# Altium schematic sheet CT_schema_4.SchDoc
size 278 x 192 mm
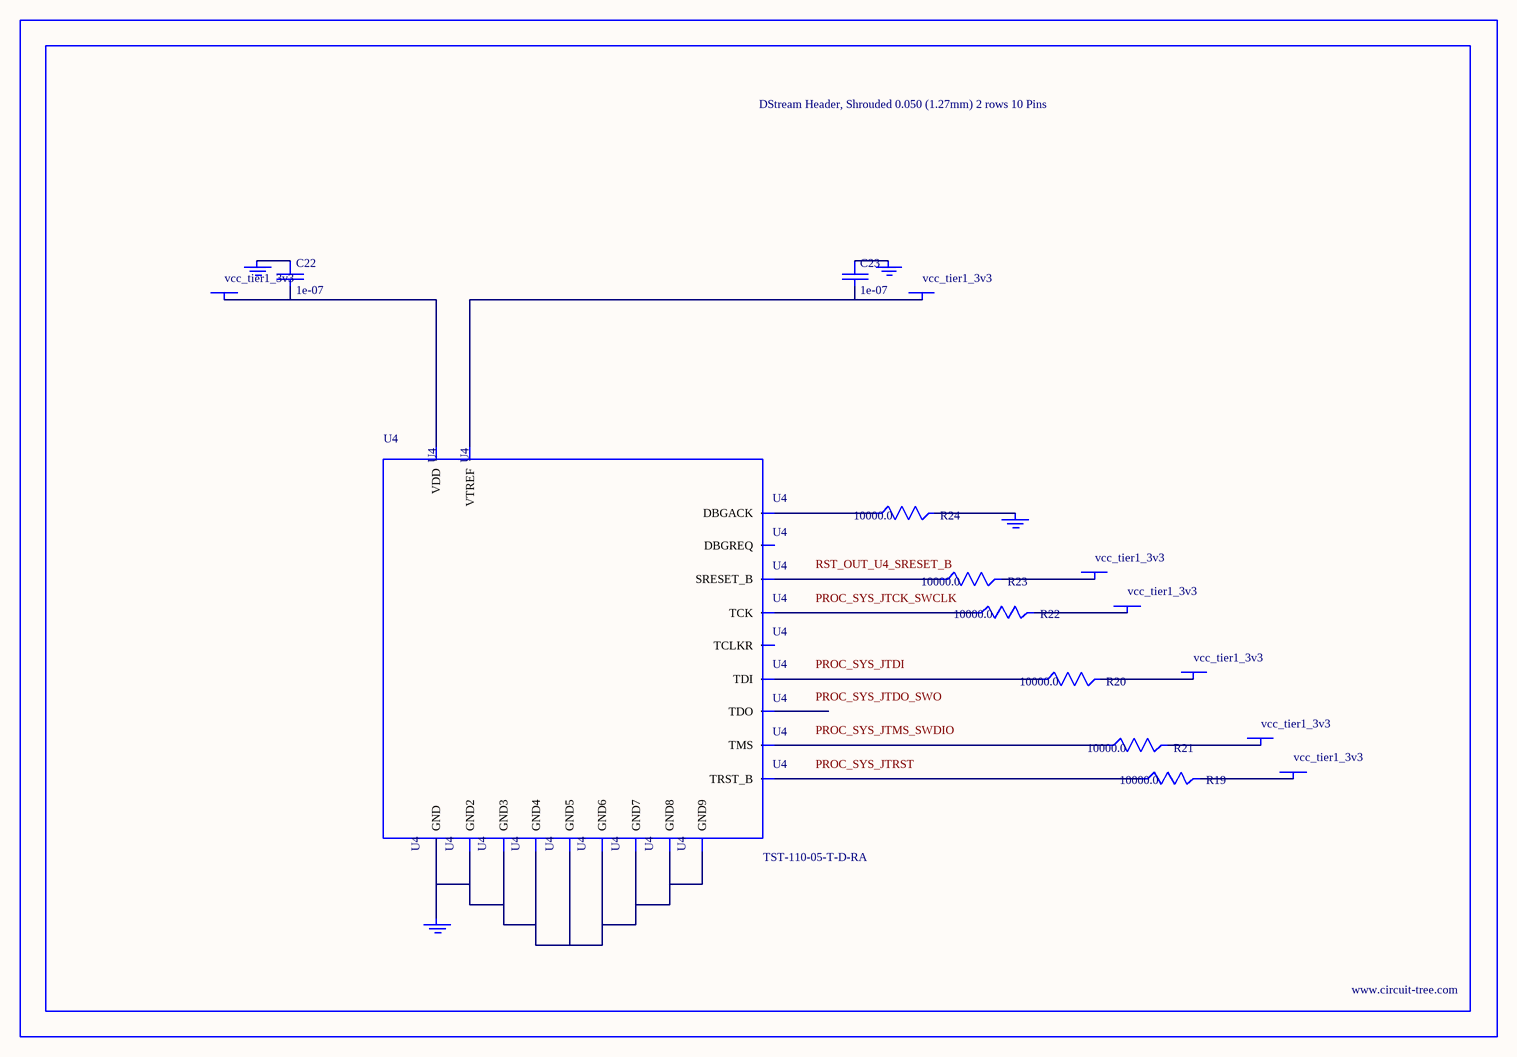
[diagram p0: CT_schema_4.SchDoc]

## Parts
BORDER3  (no value)
C22  1e-07  [C0402]
C23  1e-07  [C0402]
GND_INSTANCE_3_0  (no value)
GND_INSTANCE_3_1  (no value)
GND_INSTANCE_3_2  (no value)
GND_INSTANCE_3_3  (no value)
POWER_INSTANCE_3_0  vcc_tier1_3v3
POWER_INSTANCE_3_1  vcc_tier1_3v3
POWER_INSTANCE_3_2  vcc_tier1_3v3
POWER_INSTANCE_3_3  vcc_tier1_3v3
POWER_INSTANCE_3_4  vcc_tier1_3v3
POWER_INSTANCE_3_5  vcc_tier1_3v3
POWER_INSTANCE_3_6  vcc_tier1_3v3
R19  10000.0  [R0603]
R20  10000.0  [R0603]
R21  10000.0  [R0603]
R22  10000.0  [R0603]
R23  10000.0  [R0603]
R24  10000.0  [R0603]
U4  TST-110-05-T-D-RA  [TST-110-05-T-D-RA]

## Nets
NetC22_1: C22.1 GND_INSTANCE_3_1.0(GND)
NetC22_2: C22.2 POWER_INSTANCE_3_1.0(PWR) U4.2(VDD)
NetC23_1: C23.1 GND_INSTANCE_3_0.0(GND)
NetC23_2: C23.2 POWER_INSTANCE_3_0.0(PWR) U4.1(VTREF)
NetGND_INSTANCE_3_2_0: GND_INSTANCE_3_2.0(GND) R24.2
NetGND_INSTANCE_3_3_0: GND_INSTANCE_3_3.0(GND) U4.4(GND) U4.6(GND2) U4.8(GND3) U4.10(GND4) U4.12(GND5) U4.14(GND6) U4.16(GND7) U4.18(GND8) U4.20(GND9)
NetPOWER_INSTANCE_3_2_0: POWER_INSTANCE_3_2.0(PWR) R19.2
NetPOWER_INSTANCE_3_3_0: POWER_INSTANCE_3_3.0(PWR) R20.2
NetPOWER_INSTANCE_3_4_0: POWER_INSTANCE_3_4.0(PWR) R21.2
NetPOWER_INSTANCE_3_5_0: POWER_INSTANCE_3_5.0(PWR) R22.2
NetPOWER_INSTANCE_3_6_0: POWER_INSTANCE_3_6.0(PWR) R23.2
NetR19_1: R19.1 U4.3(TRST_B)
NetR20_1: R20.1 U4.5(TDI)
NetR21_1: R21.1 U4.7(TMS)
NetR22_1: R22.1 U4.9(TCK)
NetR23_1: R23.1 U4.15(SRESET_B)
NetR24_1: R24.1 U4.19(DBGACK)

Not connected (* = marked no-connect by the designer): U4 11(TCLKR) 13(TDO) 17(DBGREQ)

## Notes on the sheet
- Labels drawn without touching a wire or pin: PROC_SYS_JTCK_SWCLK, PROC_SYS_JTDI, PROC_SYS_JTDO_SWO, PROC_SYS_JTMS_SWDIO, PROC_SYS_JTRST, RST_OUT_U4_SRESET_B

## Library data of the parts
BORDER3 = BORDER_PAGE3
C22 C23 = C0402C104K3RACTU
GND_INSTANCE_3_0-GND_INSTANCE_3_3 = GND
POWER_INSTANCE_3_0-POWER_INSTANCE_3_6 = PWR
R19-R24 = RC0603JR-0710KL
